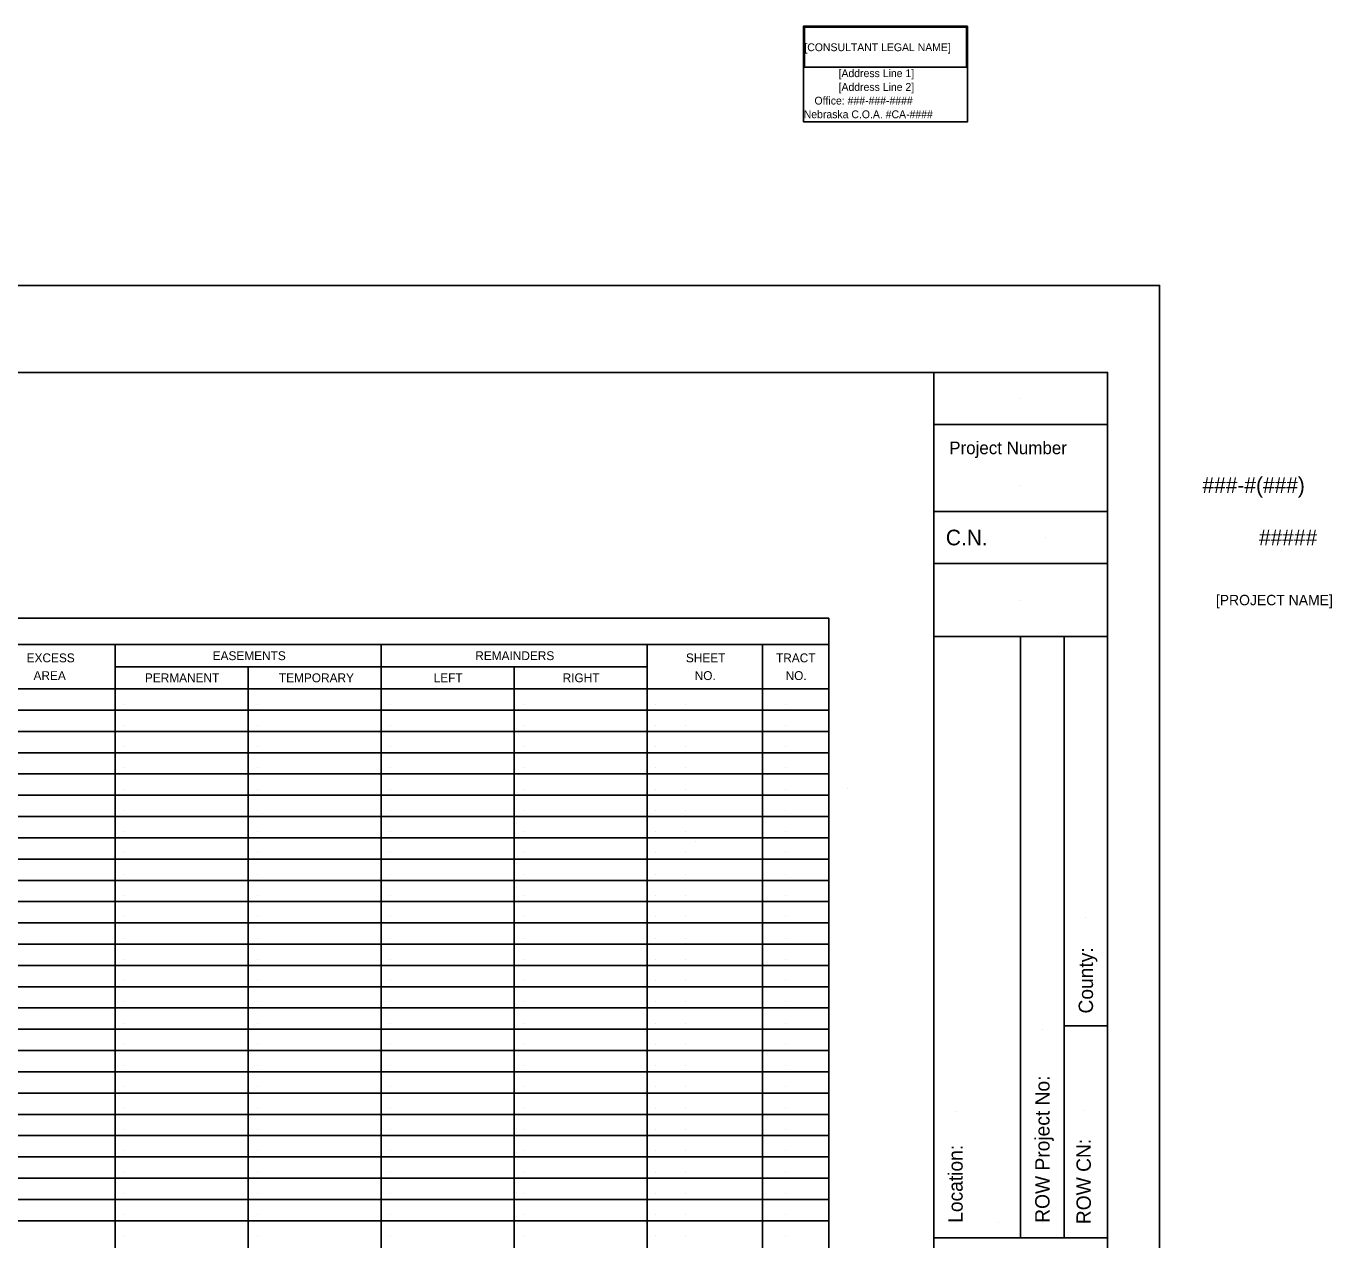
# Model space of a CAD drawing. Extents: x 0 to 3.48, y 0 to 2.25.
# Drawn here: x 1.913 to 3.165, y 1.085 to 2.249 of the extents above; entities that cross this region are included whole.
import ezdxf

# ---------------------------------------------------------------- set-up
doc = ezdxf.new("R2010")
doc.units = 0
for name, color, linetype in [('Border Active Points', 7, 'Continuous'), ('Border Line', 7, 'Continuous'), ('Border Organizer Shape', 7, 'Continuous')]:
    doc.layers.add(name, color=color, linetype=linetype)

msp = doc.modelspace()

# ---------------------------------------------------------------- linework, layer by layer
at = {"layer": 'Border Active Points'}
for p, q in [((2.8667, 1.8915), (2.8667, 1.8915)), ((2.8667, 1.8085), (2.8667, 1.8085)), ((2.8909, 1.7582), (2.8909, 1.7582)), ((2.8667, 1.6982), (2.8667, 1.6982)), ((2.007, 1.5985), (2.007, 1.5985)), ((2.1345, 1.5985), (2.1345, 1.5985)), ((2.262, 1.5985), (2.262, 1.5985)), ((2.3895, 1.5985), (2.3895, 1.5985)), ((2.517, 1.5985), (2.517, 1.5985)), ((2.5453, 1.5985), (2.5453, 1.5985)), ((2.641, 1.5985), (2.641, 1.5985)), ((2.007, 1.5781), (2.007, 1.5781)), ((2.1345, 1.5781), (2.1345, 1.5781)), ((2.262, 1.5781), (2.262, 1.5781)), ((2.3895, 1.5781), (2.3895, 1.5781)), ((2.517, 1.5781), (2.517, 1.5781)), ((2.5453, 1.5781), (2.5453, 1.5781)), ((2.641, 1.5781), (2.641, 1.5781)), ((2.007, 1.5577), (2.007, 1.5577)), ((2.1345, 1.5577), (2.1345, 1.5577)), ((2.262, 1.5577), (2.262, 1.5577)), ((2.3895, 1.5577), (2.3895, 1.5577)), ((2.517, 1.5577), (2.517, 1.5577)), ((2.5453, 1.5577), (2.5453, 1.5577)), ((2.641, 1.5577), (2.641, 1.5577)), ((2.007, 1.5373), (2.007, 1.5373)), ((2.1345, 1.5373), (2.1345, 1.5373)), ((2.262, 1.5373), (2.262, 1.5373)), ((2.3895, 1.5373), (2.3895, 1.5373)), ((2.517, 1.5373), (2.517, 1.5373)), ((2.5453, 1.5373), (2.5453, 1.5373)), ((2.641, 1.5373), (2.641, 1.5373)), ((2.007, 1.5169), (2.007, 1.5169)), ((2.1345, 1.5169), (2.1345, 1.5169)), ((2.262, 1.5169), (2.262, 1.5169)), ((2.3895, 1.5169), (2.3895, 1.5169)), ((2.517, 1.5169), (2.517, 1.5169)), ((2.5453, 1.5169), (2.5453, 1.5169)), ((2.641, 1.5169), (2.641, 1.5169)), ((2.7002, 1.5179), (2.7002, 1.5179)), ((2.007, 1.4965), (2.007, 1.4965)), ((2.1345, 1.4965), (2.1345, 1.4965)), ((2.262, 1.4965), (2.262, 1.4965)), ((2.3895, 1.4965), (2.3895, 1.4965)), ((2.517, 1.4965), (2.517, 1.4965)), ((2.5453, 1.4965), (2.5453, 1.4965)), ((2.641, 1.4965), (2.641, 1.4965)), ((2.007, 1.4761), (2.007, 1.4761)), ((2.1345, 1.4761), (2.1345, 1.4761)), ((2.262, 1.4761), (2.262, 1.4761)), ((2.3895, 1.4761), (2.3895, 1.4761)), ((2.517, 1.4761), (2.517, 1.4761)), ((2.5453, 1.4761), (2.5453, 1.4761)), ((2.5551, 1.4665), (2.5551, 1.4665)), ((2.641, 1.4761), (2.641, 1.4761)), ((2.007, 1.4557), (2.007, 1.4557)), ((2.1345, 1.4557), (2.1345, 1.4557)), ((2.262, 1.4557), (2.262, 1.4557)), ((2.3895, 1.4557), (2.3895, 1.4557)), ((2.517, 1.4557), (2.517, 1.4557)), ((2.5453, 1.4557), (2.5453, 1.4557)), ((2.641, 1.4557), (2.641, 1.4557)), ((2.007, 1.4353), (2.007, 1.4353)), ((2.1345, 1.4353), (2.1345, 1.4353)), ((2.262, 1.4353), (2.262, 1.4353)), ((2.3895, 1.4353), (2.3895, 1.4353)), ((2.517, 1.4353), (2.517, 1.4353)), ((2.5453, 1.4353), (2.5453, 1.4353)), ((2.641, 1.4353), (2.641, 1.4353)), ((2.007, 1.4149), (2.007, 1.4149)), ((2.1345, 1.4149), (2.1345, 1.4149)), ((2.262, 1.4149), (2.262, 1.4149)), ((2.3895, 1.4149), (2.3895, 1.4149)), ((2.517, 1.4149), (2.517, 1.4149)), ((2.5453, 1.4149), (2.5453, 1.4149)), ((2.641, 1.4149), (2.641, 1.4149)), ((2.007, 1.3945), (2.007, 1.3945)), ((2.1345, 1.3945), (2.1345, 1.3945)), ((2.262, 1.3945), (2.262, 1.3945)), ((2.3895, 1.3945), (2.3895, 1.3945)), ((2.517, 1.3945), (2.517, 1.3945)), ((2.5453, 1.3945), (2.5453, 1.3945)), ((2.641, 1.3945), (2.641, 1.3945)), ((2.9292, 1.394), (2.9292, 1.394)), ((2.007, 1.3741), (2.007, 1.3741)), ((2.1345, 1.3741), (2.1345, 1.3741)), ((2.262, 1.3741), (2.262, 1.3741)), ((2.3895, 1.3741), (2.3895, 1.3741)), ((2.517, 1.3741), (2.517, 1.3741)), ((2.5453, 1.3741), (2.5453, 1.3741)), ((2.641, 1.3741), (2.641, 1.3741)), ((2.007, 1.3537), (2.007, 1.3537)), ((2.1345, 1.3537), (2.1345, 1.3537)), ((2.262, 1.3537), (2.262, 1.3537)), ((2.3895, 1.3537), (2.3895, 1.3537)), ((2.517, 1.3537), (2.517, 1.3537)), ((2.5453, 1.3537), (2.5453, 1.3537)), ((2.641, 1.3537), (2.641, 1.3537)), ((2.007, 1.3333), (2.007, 1.3333)), ((2.1345, 1.3333), (2.1345, 1.3333)), ((2.262, 1.3333), (2.262, 1.3333)), ((2.3895, 1.3333), (2.3895, 1.3333)), ((2.517, 1.3333), (2.517, 1.3333)), ((2.5453, 1.3333), (2.5453, 1.3333)), ((2.641, 1.3333), (2.641, 1.3333)), ((2.007, 1.3129), (2.007, 1.3129)), ((2.1345, 1.3129), (2.1345, 1.3129)), ((2.262, 1.3129), (2.262, 1.3129)), ((2.3895, 1.3129), (2.3895, 1.3129)), ((2.517, 1.3129), (2.517, 1.3129)), ((2.5453, 1.3129), (2.5453, 1.3129)), ((2.641, 1.3129), (2.641, 1.3129)), ((2.007, 1.2925), (2.007, 1.2925)), ((2.1345, 1.2925), (2.1345, 1.2925)), ((2.262, 1.2925), (2.262, 1.2925)), ((2.3895, 1.2925), (2.3895, 1.2925)), ((2.517, 1.2925), (2.517, 1.2925)), ((2.5453, 1.2925), (2.5453, 1.2925)), ((2.641, 1.2925), (2.641, 1.2925)), ((2.8876, 1.2866), (2.8876, 1.2866)), ((2.007, 1.2721), (2.007, 1.2721)), ((2.1345, 1.2721), (2.1345, 1.2721)), ((2.262, 1.2721), (2.262, 1.2721)), ((2.3895, 1.2721), (2.3895, 1.2721)), ((2.517, 1.2721), (2.517, 1.2721)), ((2.5453, 1.2721), (2.5453, 1.2721)), ((2.641, 1.2721), (2.641, 1.2721)), ((2.007, 1.2517), (2.007, 1.2517)), ((2.1345, 1.2517), (2.1345, 1.2517)), ((2.262, 1.2517), (2.262, 1.2517)), ((2.3895, 1.2517), (2.3895, 1.2517)), ((2.517, 1.2517), (2.517, 1.2517)), ((2.5453, 1.2517), (2.5453, 1.2517)), ((2.641, 1.2517), (2.641, 1.2517)), ((2.007, 1.2313), (2.007, 1.2313)), ((2.1345, 1.2313), (2.1345, 1.2313)), ((2.262, 1.2313), (2.262, 1.2313)), ((2.3895, 1.2313), (2.3895, 1.2313)), ((2.517, 1.2313), (2.517, 1.2313)), ((2.5453, 1.2313), (2.5453, 1.2313)), ((2.641, 1.2313), (2.641, 1.2313)), ((2.007, 1.2109), (2.007, 1.2109)), ((2.1345, 1.2109), (2.1345, 1.2109)), ((2.262, 1.2109), (2.262, 1.2109)), ((2.3895, 1.2109), (2.3895, 1.2109)), ((2.517, 1.2109), (2.517, 1.2109)), ((2.5453, 1.2109), (2.5453, 1.2109)), ((2.641, 1.2109), (2.641, 1.2109)), ((2.8043, 1.2077), (2.8043, 1.2077)), ((2.9272, 1.2085), (2.9272, 1.2085)), ((2.007, 1.1905), (2.007, 1.1905)), ((2.1345, 1.1905), (2.1345, 1.1905)), ((2.262, 1.1905), (2.262, 1.1905)), ((2.3895, 1.1905), (2.3895, 1.1905)), ((2.517, 1.1905), (2.517, 1.1905)), ((2.5453, 1.1905), (2.5453, 1.1905)), ((2.641, 1.1905), (2.641, 1.1905)), ((2.007, 1.1701), (2.007, 1.1701)), ((2.1345, 1.1701), (2.1345, 1.1701)), ((2.262, 1.1701), (2.262, 1.1701)), ((2.3895, 1.1701), (2.3895, 1.1701)), ((2.517, 1.1701), (2.517, 1.1701)), ((2.5453, 1.1701), (2.5453, 1.1701)), ((2.641, 1.1701), (2.641, 1.1701)), ((2.007, 1.1497), (2.007, 1.1497)), ((2.1345, 1.1497), (2.1345, 1.1497)), ((2.262, 1.1497), (2.262, 1.1497)), ((2.3895, 1.1497), (2.3895, 1.1497)), ((2.517, 1.1497), (2.517, 1.1497)), ((2.5453, 1.1497), (2.5453, 1.1497)), ((2.641, 1.1497), (2.641, 1.1497)), ((2.007, 1.1293), (2.007, 1.1293)), ((2.1345, 1.1293), (2.1345, 1.1293)), ((2.262, 1.1293), (2.262, 1.1293)), ((2.3895, 1.1293), (2.3895, 1.1293)), ((2.517, 1.1293), (2.517, 1.1293)), ((2.5453, 1.1293), (2.5453, 1.1293)), ((2.641, 1.1293), (2.641, 1.1293)), ((2.007, 1.1089), (2.007, 1.1089)), ((2.1345, 1.1089), (2.1345, 1.1089)), ((2.262, 1.1089), (2.262, 1.1089)), ((2.3895, 1.1089), (2.3895, 1.1089)), ((2.517, 1.1089), (2.517, 1.1089)), ((2.5453, 1.1089), (2.5453, 1.1089)), ((2.641, 1.1089), (2.641, 1.1089)), ((2.8042, 1.101), (2.8042, 1.101)), ((2.8459, 1.101), (2.8459, 1.101)), ((2.8875, 1.101), (2.8875, 1.101)), ((2.9275, 1.101), (2.9275, 1.101)), ((2.007, 1.0885), (2.007, 1.0885)), ((2.1345, 1.0885), (2.1345, 1.0885)), ((2.262, 1.0885), (2.262, 1.0885)), ((2.3895, 1.0885), (2.3895, 1.0885)), ((2.517, 1.0885), (2.517, 1.0885)), ((2.5453, 1.0885), (2.5453, 1.0885)), ((2.641, 1.0885), (2.641, 1.0885))]:
    msp.add_line(p, q, dxfattribs=at)
at = {"layer": 'Border Line'}
for p, q in [((2.6585, 2.1568), (2.6585, 2.2486)), ((2.6585, 2.1568), (2.6585, 2.2486)), ((2.6585, 2.2486), (2.8157, 2.2486)), ((2.8157, 2.1568), (2.8157, 2.2486)), ((2.6585, 2.1568), (2.8157, 2.1568)), ((2.6585, 2.1568), (2.8157, 2.1568)), ((2.7834, 0.0835), (2.7834, 1.9165)), ((2.7834, 1.8665), (2.95, 1.8665)), ((2.7834, 1.7832), (2.95, 1.7832)), ((2.7834, 1.7332), (2.95, 1.7332)), ((0.2177, 1.681), (2.6827, 1.681)), ((2.6827, 1.681), (2.6827, 0.185)), ((0.2177, 1.6555), (2.6827, 1.6555)), ((1.9985, 1.6555), (1.9985, 0.185)), ((2.2535, 1.6555), (2.2535, 0.185)), ((2.5085, 1.6555), (2.5085, 0.185)), ((2.619, 1.6555), (2.619, 0.185)), ((2.7834, 1.6632), (2.95, 1.6632)), ((2.8667, 1.0866), (2.8667, 1.6632)), ((2.9084, 1.6632), (2.9084, 1.0866)), ((1.9985, 1.6342), (2.5085, 1.6342)), ((2.126, 1.6342), (2.126, 0.185)), ((2.381, 1.6342), (2.381, 0.185)), ((0.2177, 1.613), (2.6827, 1.613)), ((0.2177, 1.5926), (2.6827, 1.5926)), ((0.2177, 1.5722), (2.6827, 1.5722)), ((0.2177, 1.5518), (2.6827, 1.5518)), ((0.2177, 1.5314), (2.6827, 1.5314)), ((0.2177, 1.511), (2.6827, 1.511)), ((0.2177, 1.4906), (2.6827, 1.4906)), ((0.2177, 1.4702), (2.6827, 1.4702)), ((0.2177, 1.4498), (2.6827, 1.4498)), ((0.2177, 1.4294), (2.6827, 1.4294)), ((0.2177, 1.409), (2.6827, 1.409)), ((0.2177, 1.3886), (2.6827, 1.3886)), ((0.2177, 1.3682), (2.6827, 1.3682)), ((0.2177, 1.3478), (2.6827, 1.3478)), ((0.2177, 1.3274), (2.6827, 1.3274)), ((0.2177, 1.307), (2.6827, 1.307)), ((2.95, 1.2898), (2.9084, 1.2898)), ((0.2177, 1.2866), (2.6827, 1.2866)), ((0.2177, 1.2662), (2.6827, 1.2662)), ((0.2177, 1.2458), (2.6827, 1.2458)), ((0.2177, 1.2254), (2.6827, 1.2254)), ((0.2177, 1.205), (2.6827, 1.205)), ((0.2177, 1.1846), (2.6827, 1.1846)), ((0.2177, 1.1642), (2.6827, 1.1642)), ((0.2177, 1.1438), (2.6827, 1.1438)), ((0.2177, 1.1234), (2.6827, 1.1234)), ((0.2177, 1.103), (2.6827, 1.103)), ((2.7834, 1.0866), (2.95, 1.0866))]:
    msp.add_line(p, q, dxfattribs=at)
for points in [[(2.8157, 2.2486), (2.6585, 2.2486), (2.6585, 2.1568), (2.8157, 2.1568)], [(2.8147, 2.2476), (2.6595, 2.2476), (2.6595, 2.2092), (2.8147, 2.2092)], [(0.117, 0.0835), (2.95, 0.0835), (2.95, 1.9165), (0.117, 1.9165)]]:
    msp.add_lwpolyline(points, close=True, dxfattribs=at)
at = {"layer": 'Border Organizer Shape'}
msp.add_lwpolyline([(3, 0), (0, 0), (0, 2), (3, 2)], close=True, dxfattribs=at)

# ---------------------------------------------------------------- texts
at = {"layer": 'Border Line'}
for s, height, p in [('[CONSULTANT LEGAL NAME]', 0.0075, (2.6593, 2.2246)), ('Project Number', 0.01215, (2.7982, 1.8381)), ('###-#(###)', 0.015, (3.0411, 1.801)), ('C.N.', 0.015, (2.795, 1.7507)), ('#####', 0.015, (3.0953, 1.7507)), ('[PROJECT NAME]', 0.01, (3.0539, 1.6932)), ('EXCESS', 0.0085, (1.9135, 1.6385)), ('EASEMENTS', 0.0085, (2.0919, 1.6406)), ('REMAINDERS', 0.0085, (2.3437, 1.6406)), ('SHEET', 0.0085, (2.5457, 1.6385)), ('TRACT', 0.0085, (2.6321, 1.6385)), ('AREA', 0.0085, (1.9201, 1.6215)), ('PERMANENT', 0.0085, (2.0269, 1.6194)), ('TEMPORARY', 0.0085, (2.1554, 1.6194)), ('LEFT', 0.0085, (2.3038, 1.6194)), ('RIGHT', 0.0085, (2.4275, 1.6194)), ('NO.', 0.0085, (2.5541, 1.6215)), ('NO.', 0.0085, (2.6413, 1.6215))]:
    msp.add_text(s, height=height, dxfattribs=at).set_placement(p)
for s, height, rotation, p in [('[Address Line 1]', 0.0075, 360, (2.6921, 2.1997)), ('[Address Line 2]', 0.0075, 360, (2.6921, 2.1865)), ('Office: ###-###-####', 0.0075, 360, (2.669, 2.1734)), ('Nebraska C.O.A. #CA-####', 0.0075, 360, (2.6587, 2.1603)), ('County:', 0.01377, 90, (2.9361, 1.3017)), ('ROW Project No:', 0.01377, 90, (2.8944, 1.101)), ('ROW CN:', 0.01377, 90, (2.934, 1.0997)), ('Location:', 0.01377, 90, (2.8111, 1.101))]:
    msp.add_text(s, height=height, rotation=rotation, dxfattribs=at).set_placement(p)

doc.saveas('drawing.dxf')
